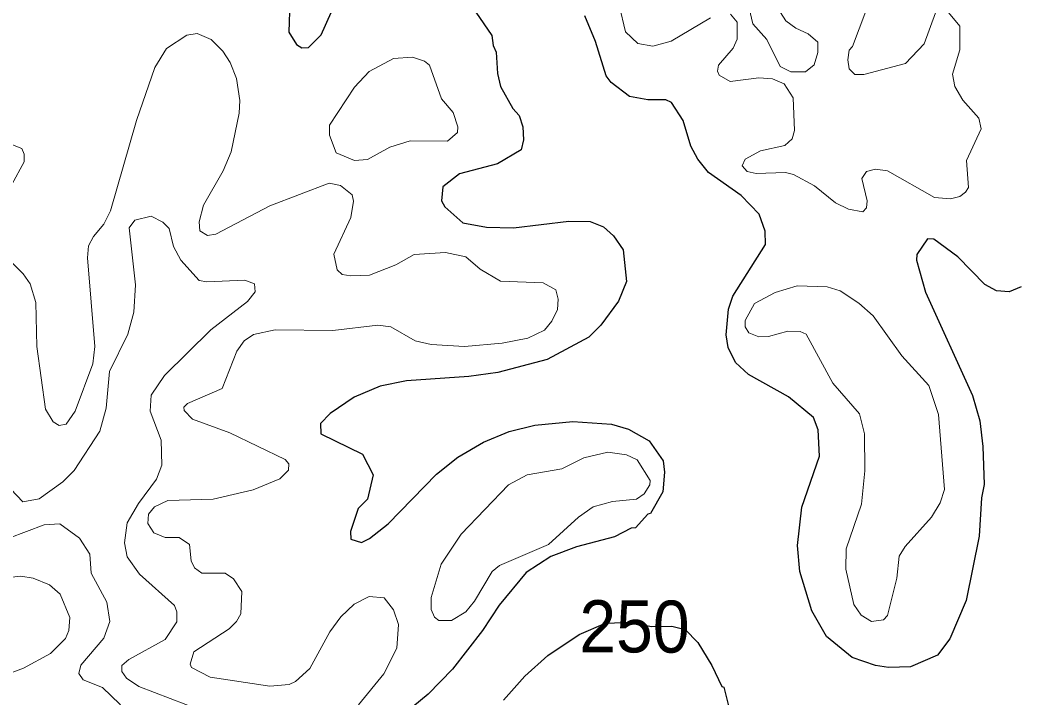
# Model space of a CAD drawing. Extents: x 763.2 to 816.8, y 7896.5 to 7952.7.
# Drawn here: x 807.081 to 810.159, y 7918.534 to 7920.619 of the extents above; entities that cross this region are included whole.
import ezdxf
from ezdxf.enums import TextEntityAlignment as Align

# ---------------------------------------------------------------- set-up
doc = ezdxf.new("R2010")
doc.units = 0
doc.header["$LTSCALE"] = 0.064
doc.layers.add('1', color=7, linetype='Continuous', lineweight=25)
doc.layers.add('2', color=7, linetype='Continuous', lineweight=13)
doc.layers.add('61', color=7, linetype='Continuous')

msp = doc.modelspace()

# ---------------------------------------------------------------- linework, layer by layer
at = {"layer": '1'}
for points in [[(807.9109, 7920.6768), (807.9078, 7920.5818), (807.9309, 7920.5436), (807.9472, 7920.5338), (807.9679, 7920.5344), (808.0066, 7920.5734), (808.0379, 7920.6427)], [(808.4828, 7920.6435), (808.5322, 7920.572), (808.5355, 7920.541), (808.5452, 7920.521), (808.5488, 7920.4546), (808.5588, 7920.4146), (808.5961, 7920.347), (808.6157, 7920.3254), (808.6274, 7920.2903), (808.6291, 7920.251), (808.6217, 7920.2205), (808.5493, 7920.1773), (808.432, 7920.1462), (808.3813, 7920.1061), (808.3765, 7920.0636), (808.3868, 7920.0451), (808.4429, 7919.995), (808.5159, 7919.9817), (808.5987, 7919.9798), (808.7682, 7920.0005), (808.8346, 7919.9993), (808.8754, 7919.9834), (808.9063, 7919.9555), (808.9362, 7919.9123), (808.9463, 7919.8152), (808.9216, 7919.7546), (808.8674, 7919.6806), (808.8302, 7919.6434), (808.7024, 7919.5752), (808.5507, 7919.5354), (808.4612, 7919.5223), (808.2693, 7919.5097), (808.1887, 7919.4927), (808.1085, 7919.4586), (808.0349, 7919.4083), (808.0051, 7919.3781), (808.0059, 7919.3461), (808.1338, 7919.2832), (808.1668, 7919.2203), (808.1494, 7919.1455), (808.1211, 7919.1161), (808.097, 7919.0454), (808.0979, 7919.0226), (808.1305, 7919.0122), (808.1556, 7919.0243), (808.2134, 7919.0693), (808.3614, 7919.2221), (808.4277, 7919.2744), (808.5066, 7919.321), (808.5848, 7919.3535), (808.6638, 7919.3732), (808.7813, 7919.3847), (808.9003, 7919.3765), (808.9522, 7919.361), (809.0158, 7919.3243), (809.0586, 7919.2634)], [(810.16, 7919.7987), (810.1231, 7919.7828), (810.0838, 7919.7861), (810.0479, 7919.806), (809.9652, 7919.8909), (809.8913, 7919.9449), (809.8724, 7919.9466), (809.8386, 7919.8979), (809.8377, 7919.8803), (809.866, 7919.7825), (810.0099, 7919.4646), (810.0326, 7919.3864), (810.0425, 7919.3075), (810.0457, 7919.19), (810.0376, 7919.1491), (810.031, 7919.0314), (809.9913, 7918.8335), (809.9406, 7918.716), (809.9026, 7918.6651), (809.8193, 7918.6295), (809.7524, 7918.6272), (809.7115, 7918.6339), (809.6406, 7918.6582), (809.5616, 7918.7225), (809.5164, 7918.8016), (809.4789, 7918.9231), (809.4723, 7919.0026), (809.4856, 7919.121), (809.5394, 7919.2772), (809.5357, 7919.3585), (809.5213, 7919.3962), (809.4443, 7919.4597), (809.3209, 7919.5285), (809.2817, 7919.5655), (809.2592, 7919.6116), (809.2524, 7919.6509), (809.26, 7919.7298), (809.2729, 7919.7693), (809.3734, 7919.9288), (809.373, 7919.9699), (809.354, 7920.0217), (809.2986, 7920.0793), (809.1985, 7920.1502), (809.1655, 7920.1911), (809.1436, 7920.2312), (809.1204, 7920.31), (809.0843, 7920.3657), (809.0666, 7920.3741), (809.0121, 7920.3742), (808.9552, 7920.3839), (808.8986, 7920.4271), (808.8833, 7920.448), (808.8509, 7920.5533), (808.8181, 7920.6322)], [(809.0586, 7919.2634), (809.0629, 7919.2287), (809.0583, 7919.1678), (809.0194, 7919.1014), (809.0117, 7919.0996), (808.974, 7919.0566)], [(808.974, 7919.0566), (808.9607, 7919.0556), (808.9095, 7919.0297), (808.7919, 7918.9985), (808.7138, 7918.9692), (808.6375, 7918.9196), (808.5541, 7918.8196), (808.5032, 7918.7407), (808.4109, 7918.6224), (808.3356, 7918.5455), (808.1942, 7918.4288)], [(808.5679, 7918.5266), (808.6336, 7918.6003), (808.7038, 7918.6638), (808.8002, 7918.729), (808.8817, 7918.7635), (808.9648, 7918.7673), (809.0214, 7918.7535), (809.0856, 7918.7547), (809.1269, 7918.7443), (809.1653, 7918.7043), (809.2085, 7918.6334), (809.239, 7918.5687), (809.2455, 7918.5669), (809.2618, 7918.5008)]]:
    msp.add_lwpolyline(points, dxfattribs=at)
at = {"layer": '2'}
msp.add_line((809.9919, 7920.1867), (810.0373, 7920.2843), dxfattribs=at)
for points in [[(808.9036, 7920.7479), (808.9432, 7920.5834), (808.9804, 7920.5473), (809.0272, 7920.5388), (809.0832, 7920.5542), (809.2048, 7920.6264)], [(809.8964, 7920.6418), (809.8612, 7920.5462), (809.8039, 7920.4861), (809.676, 7920.4514), (809.6483, 7920.452), (809.6305, 7920.4697), (809.6267, 7920.4965), (809.6313, 7920.527), (809.6415, 7920.5377), (809.6819, 7920.6464)], [(809.2656, 7920.637), (809.2862, 7920.6123), (809.2864, 7920.56), (809.2745, 7920.5331), (809.2293, 7920.4809), (809.226, 7920.462), (809.2312, 7920.4495), (809.2651, 7920.4301), (809.3532, 7920.4414), (809.3948, 7920.4381), (809.4314, 7920.4229), (809.4583, 7920.3804), (809.4624, 7920.2799), (809.4554, 7920.2543), (809.4326, 7920.2331), (809.3586, 7920.2168), (809.3114, 7920.1914), (809.3016, 7920.1708), (809.317, 7920.153), (809.3448, 7920.1474), (809.4354, 7920.1506), (809.4598, 7920.1438), (809.5248, 7920.1095), (809.5885, 7920.0569), (809.6294, 7920.0375), (809.6732, 7920.0294), (809.6842, 7920.0415), (809.6858, 7920.0628), (809.6697, 7920.1323), (809.6845, 7920.1535), (809.7118, 7920.1603), (809.7487, 7920.1551), (809.8931, 7920.0735), (809.9428, 7920.0692), (809.9712, 7920.0765), (809.9892, 7920.0896), (809.9977, 7920.1044), (809.9919, 7920.1867)], [(810.0373, 7920.2843), (810.0303, 7920.3175), (809.9801, 7920.3726), (809.9557, 7920.4152), (809.9491, 7920.4532), (809.9718, 7920.5277), (809.9715, 7920.6004), (809.9366, 7920.6422)], [(807.76, 7918.7921), (807.7629, 7918.8614), (807.7368, 7918.8999), (807.7111, 7918.9175), (807.6403, 7918.9173), (807.6177, 7918.9342), (807.6072, 7918.9552), (807.6014, 7919.0054), (807.5697, 7919.0276), (807.5266, 7919.0268), (807.4918, 7919.042), (807.4738, 7919.07), (807.4762, 7919.0989), (807.4937, 7919.1219), (807.5351, 7919.1411), (807.6743, 7919.1449), (807.7979, 7919.174), (807.8802, 7919.2083), (807.9068, 7919.2342), (807.9076, 7919.2542), (807.8959, 7919.2675), (807.7263, 7919.3489), (807.6115, 7919.3918), (807.5851, 7919.4179), (807.5841, 7919.4286), (807.5957, 7919.4391), (807.7021, 7919.4855), (807.7471, 7919.6007), (807.7704, 7919.632), (807.7986, 7919.6522), (807.865, 7919.6658), (808.0432, 7919.6643), (808.1812, 7919.6806), (808.2214, 7919.6751), (808.2962, 7919.6328), (808.3449, 7919.6215), (808.4474, 7919.6149), (808.5632, 7919.625), (808.6427, 7919.6407), (808.6937, 7919.6647), (808.7167, 7919.6928), (808.7342, 7919.7283), (808.736, 7919.7605), (808.7289, 7919.7892), (808.6894, 7919.8105), (808.558, 7919.8157), (808.4961, 7919.8532), (808.4519, 7919.8911), (808.389, 7919.904), (808.293, 7919.8976), (808.2364, 7919.8664), (808.1552, 7919.8346), (808.0983, 7919.8319), (808.0715, 7919.8366), (808.0556, 7919.8507), (808.0458, 7919.8995), (808.0981, 7920.012), (808.1062, 7920.0621), (808.1027, 7920.0813), (808.0661, 7920.1107), (808.0315, 7920.1173), (807.8492, 7920.0473), (807.683, 7919.9609), (807.6568, 7919.9568), (807.6332, 7919.9713), (807.6321, 7919.998), (807.6445, 7920.0498), (807.7051, 7920.1549), (807.7298, 7920.2134), (807.7546, 7920.3324), (807.7565, 7920.3718), (807.7461, 7920.4395), (807.7266, 7920.4882), (807.7043, 7920.5233), (807.668, 7920.5598), (807.625, 7920.5777), (807.5936, 7920.5732), (807.5314, 7920.5319), (807.495, 7920.4738), (807.4387, 7920.3101), (807.3593, 7920.032), (807.3387, 7919.991), (807.3063, 7919.9534), (807.2915, 7919.9242), (807.2882, 7919.8879), (807.311, 7919.6147), (807.3045, 7919.5613), (807.2499, 7919.4155), (807.2222, 7919.3763), (807.2011, 7919.3719), (807.183, 7919.3834), (807.1585, 7919.4221), (807.1324, 7919.6154), (807.1288, 7919.7499), (807.1114, 7919.8082)], [(807.0168, 7920.0432), (807.0935, 7920.1829), (807.0938, 7920.2069), (807.0859, 7920.2241), (807.047, 7920.2391)], [(807.1114, 7919.8082), (807.0904, 7919.8387), (807.0166, 7919.9124), (807.0005, 7919.9656), (807.0017, 7920.002), (807.0168, 7920.0432)], [(807.0518, 7919.1755), (807.0895, 7919.137), (807.139, 7919.1462), (807.212, 7919.1985), (807.247, 7919.2336), (807.3261, 7919.3542), (807.346, 7919.4251), (807.3558, 7919.5383), (807.4117, 7919.6533), (807.4308, 7919.7203), (807.436, 7919.8045), (807.4164, 7919.9798), (807.4341, 7920.0038), (807.4842, 7920.0158), (807.5197, 7919.9976), (807.5396, 7919.9777), (807.5529, 7919.9231), (807.5754, 7919.8801), (807.6313, 7919.8184), (807.6554, 7919.8138), (807.7722, 7919.8186), (807.8019, 7919.8073), (807.8035, 7919.7831), (807.78, 7919.7537), (807.6678, 7919.6658), (807.5248, 7919.526), (807.4839, 7919.4653), (807.4805, 7919.4156), (807.5149, 7919.3272), (807.5168, 7919.2498), (807.5005, 7919.2064), (807.4451, 7919.132), (807.4104, 7919.0723), (807.4017, 7919.0111), (807.4105, 7918.9677), (807.4477, 7918.9144), (807.5554, 7918.8183), (807.5624, 7918.7985), (807.5625, 7918.7681), (807.5266, 7918.7131), (807.4153, 7918.6522), (807.3939, 7918.6335), (807.3934, 7918.6155), (807.4079, 7918.5947), (807.4463, 7918.5687), (807.6869, 7918.4762)], [(807.2029, 7919.0692), (807.155, 7919.0659), (807.0458, 7919.0249), (806.9592, 7919.007), (806.9126, 7919.0246), (806.9035, 7919.0496)], [(806.9637, 7918.4415), (807.1041, 7918.4197), (807.2239, 7918.3735), (807.3384, 7918.3497), (807.3913, 7918.3695), (807.4061, 7918.387), (807.4178, 7918.4169), (807.4196, 7918.4491), (807.4083, 7918.4819), (807.3875, 7918.5142), (807.3341, 7918.5663), (807.2751, 7918.5898), (807.2619, 7918.6089), (807.2674, 7918.6346), (807.3382, 7918.718), (807.357, 7918.7686), (807.3475, 7918.8282), (807.2996, 7918.9171), (807.2957, 7918.9761), (807.2633, 7919.0248), (807.2029, 7919.0692)], [(806.8926, 7918.5502), (807.0914, 7918.6248), (807.1738, 7918.6705), (807.2207, 7918.7163), (807.2303, 7918.7414), (807.2338, 7918.7809), (807.2045, 7918.8532), (807.1713, 7918.8818), (807.1215, 7918.9017), (807.0834, 7918.908), (806.9881, 7918.8985)], [(808.1218, 7918.5127), (808.2001, 7918.6075), (808.2395, 7918.6864), (808.2448, 7918.7593), (808.2294, 7918.8052), (808.2007, 7918.8416), (808.1543, 7918.8455), (808.1083, 7918.8227), (808.0671, 7918.7834), (808.0335, 7918.7368), (807.9718, 7918.6243), (807.9277, 7918.5843), (807.9083, 7918.5749), (807.8485, 7918.5697), (807.6652, 7918.5974), (807.6084, 7918.6278)], [(807.6084, 7918.6278), (807.604, 7918.6372), (807.6154, 7918.6758), (807.7241, 7918.746), (807.7468, 7918.7686), (807.76, 7918.7921)]]:
    msp.add_lwpolyline(points, dxfattribs=at)
for points in [[(809.5044, 7920.5765), (809.4671, 7920.5939), (809.4363, 7920.6174), (809.4106, 7920.6571), (809.3983, 7920.6979), (809.3859, 7920.7168), (809.3678, 7920.7268), (809.3406, 7920.7282), (809.3162, 7920.6873), (809.3351, 7920.608), (809.3772, 7920.5592), (809.4183, 7920.4763), (809.4519, 7920.4596), (809.497, 7920.4596), (809.5238, 7920.4816), (809.5345, 7920.519), (809.5346, 7920.5509)], [(808.2181, 7920.2286), (808.2805, 7920.2478), (808.3958, 7920.2462), (808.4266, 7920.2736), (808.4268, 7920.291), (808.4127, 7920.3351), (808.3771, 7920.3771), (808.3401, 7920.4804), (808.3244, 7920.4926), (808.2876, 7920.5056), (808.2298, 7920.5006), (808.1549, 7920.4615), (808.1094, 7920.4129), (808.0327, 7920.2956), (808.0327, 7920.2647), (808.053, 7920.2112), (808.1089, 7920.1868), (808.1498, 7920.1902)], [(809.6793, 7919.2326), (809.6778, 7919.3463), (809.6626, 7919.4077), (809.5807, 7919.5023), (809.4984, 7919.6524), (809.4802, 7919.6606), (809.4427, 7919.6624), (809.3828, 7919.646), (809.3535, 7919.6445), (809.3224, 7919.6569), (809.3115, 7919.6758), (809.3114, 7919.6946), (809.3399, 7919.7477), (809.4032, 7919.7808), (809.4709, 7919.8019), (809.5628, 7919.799), (809.6031, 7919.7859), (809.6609, 7919.7479), (809.7045, 7919.7096), (809.7932, 7919.5864), (809.8763, 7919.4947), (809.9061, 7919.4054), (809.9238, 7919.1747), (809.9112, 7919.1338), (809.8846, 7919.0896), (809.8037, 7918.9999), (809.785, 7918.9694), (809.7776, 7918.902), (809.7487, 7918.7875), (809.7366, 7918.7738), (809.6997, 7918.7686), (809.6683, 7918.7882), (809.6451, 7918.8215), (809.6202, 7918.9302), (809.6219, 7918.992), (809.6692, 7919.1294)], [(808.4376, 7919.0377), (808.5831, 7919.189), (808.6401, 7919.2201), (808.7467, 7919.239), (808.8151, 7919.2729), (808.8887, 7919.2894), (808.9464, 7919.2812), (808.9787, 7919.2666), (809.0184, 7919.2023), (809.0182, 7919.1889), (809, 7919.1616), (808.9767, 7919.1449), (808.903, 7919.138), (808.8439, 7919.1215), (808.7979, 7919.0902), (808.7059, 7919.006), (808.5553, 7918.9409), (808.5325, 7918.9228), (808.4783, 7918.8315), (808.4521, 7918.7987), (808.4078, 7918.772), (808.3693, 7918.7718), (808.3554, 7918.7826), (808.3447, 7918.8059), (808.3447, 7918.8427), (808.3755, 7918.945)]]:
    msp.add_lwpolyline(points, close=True, dxfattribs=at)

# ---------------------------------------------------------------- texts
at = {"layer": '61', "width": 0.95}
msp.add_text('250', height=0.16, rotation=359.712, dxfattribs=at).set_placement((808.9702, 7918.6737), align=Align.CENTER)

doc.saveas('drawing.dxf')
